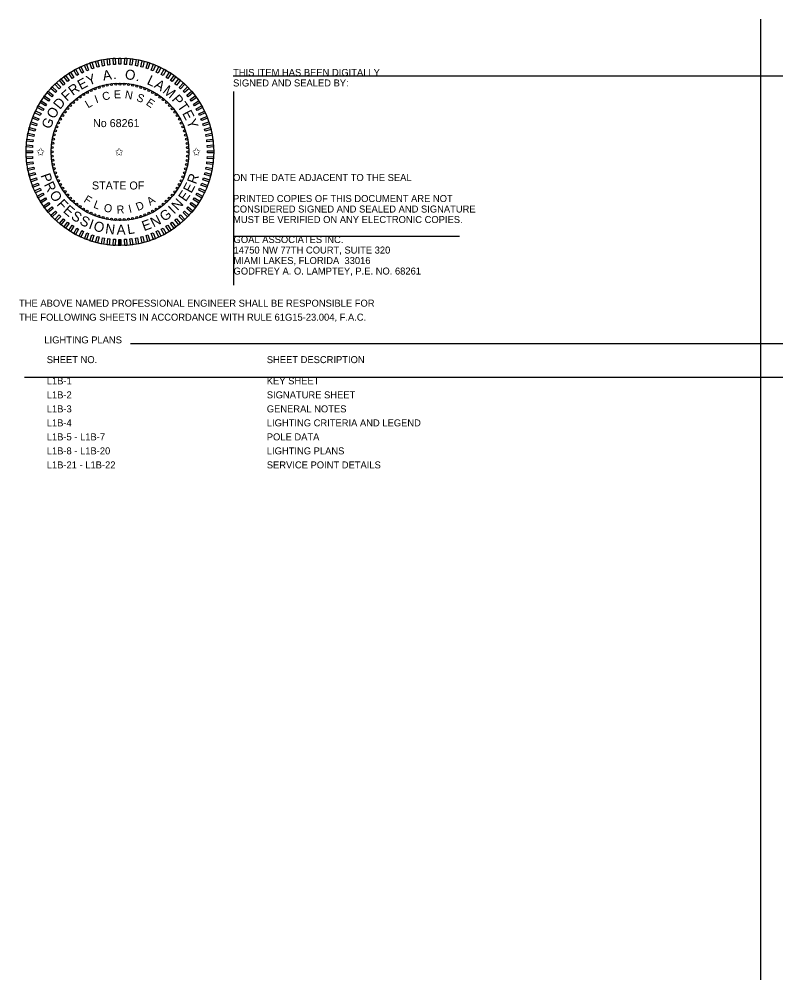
# Model space of a CAD drawing. Extents: x -811.2 to -795, y -2307.6 to -2235.1.
# Drawn here: x -810.5 to -802.94, y -2244.66 to -2235.06 of the extents above; entities that cross this region are included whole.
import ezdxf

# ---------------------------------------------------------------- set-up
doc = ezdxf.new("R2010")
doc.units = 0
for name, color, linetype in [('AdhocPoint_dp', 7, 'Continuous'), ('Logo_dp', 7, 'Continuous'), ('TeleMisc', 7, 'Continuous'), ('TextDetails', 7, 'Continuous'), ('TextMisc', 7, 'Continuous'), ('TextNotes', 7, 'Continuous')]:
    doc.layers.add(name, color=color, linetype=linetype)

msp = doc.modelspace()

# ---------------------------------------------------------------- linework, layer by layer
at = {"layer": 'AdhocPoint_dp'}
for p, q in [((-808.3596, -2235.6292), (-796.8708, -2235.6292)), ((-808.3546, -2235.7843), (-808.3546, -2237.719)), ((-808.3546, -2237.229), (-806.0979, -2237.229)), ((-809.3854, -2238.3022), (-800.7818, -2238.3022)), ((-801.9648, -2238.6414), (-810.4432, -2238.6414))]:
    msp.add_line(p, q, dxfattribs=at)
at = {"layer": 'TextDetails'}
for radius in [0.9375, 0.6875]:
    msp.add_circle((-809.4901, -2236.3877), radius, dxfattribs=at)
at = {"layer": 'TextMisc'}
for p, q in [((-809.5001, -2237.3253), (-809.5003, -2237.2628)), ((-809.4901, -2237.3252), (-809.4903, -2237.2627)), ((-809.4801, -2237.3252), (-809.4803, -2237.2627))]:
    msp.add_line(p, q, dxfattribs=at)
for points in [[(-809.5349, -2235.5138), (-809.555, -2235.5151), (-809.559, -2235.4527), (-809.5388, -2235.4515)], [(-809.4799, -2235.5127), (-809.5001, -2235.5127), (-809.5001, -2235.4503), (-809.4799, -2235.4503)], [(-809.425, -2235.5151), (-809.4452, -2235.5138), (-809.4412, -2235.4515), (-809.4211, -2235.4528)], [(-809.8535, -2235.5917), (-809.8717, -2235.6002), (-809.8983, -2235.5438), (-809.8801, -2235.5352)], [(-809.8028, -2235.5704), (-809.8215, -2235.5778), (-809.8445, -2235.5198), (-809.8258, -2235.5124)], [(-809.7508, -2235.5524), (-809.77, -2235.5586), (-809.7893, -2235.4992), (-809.7701, -2235.493)], [(-809.6979, -2235.5377), (-809.7174, -2235.5427), (-809.7329, -2235.4822), (-809.7134, -2235.4772)], [(-809.6441, -2235.5263), (-809.6639, -2235.5301), (-809.6756, -2235.4688), (-809.6558, -2235.465)], [(-809.5897, -2235.5183), (-809.6097, -2235.5209), (-809.6175, -2235.4589), (-809.5975, -2235.4564)], [(-809.3703, -2235.5209), (-809.3904, -2235.5184), (-809.3825, -2235.4564), (-809.3625, -2235.4589)], [(-809.3162, -2235.5301), (-809.336, -2235.5263), (-809.3243, -2235.465), (-809.3045, -2235.4688)], [(-809.2626, -2235.5427), (-809.2822, -2235.5377), (-809.2667, -2235.4772), (-809.2471, -2235.4823)], [(-809.21, -2235.5587), (-809.2292, -2235.5524), (-809.2099, -2235.4931), (-809.1907, -2235.4993)], [(-809.1585, -2235.5779), (-809.1773, -2235.5705), (-809.1543, -2235.5124), (-809.1355, -2235.5199)], [(-809.1083, -2235.6003), (-809.1266, -2235.5917), (-809.1, -2235.5352), (-809.0817, -2235.5438)], [(-809.9962, -2235.6738), (-810.0125, -2235.6857), (-810.0492, -2235.6352), (-810.0329, -2235.6233)], [(-809.9504, -2235.6435), (-809.9674, -2235.6543), (-810.0009, -2235.6016), (-809.9838, -2235.5908)], [(-809.9027, -2235.616), (-809.9204, -2235.6258), (-809.9505, -2235.571), (-809.9328, -2235.5613)], [(-809.0596, -2235.6259), (-809.0773, -2235.6161), (-809.0473, -2235.5614), (-809.0296, -2235.5711)], [(-809.0127, -2235.6544), (-809.0297, -2235.6436), (-808.9962, -2235.5909), (-808.9792, -2235.6017)], [(-808.9676, -2235.6858), (-808.9839, -2235.674), (-808.9472, -2235.6234), (-808.9308, -2235.6353)], [(-810.121, -2235.7813), (-810.1348, -2235.796), (-810.1804, -2235.7533), (-810.1665, -2235.7386)], [(-810.0817, -2235.7429), (-810.0964, -2235.7567), (-810.1392, -2235.7112), (-810.1244, -2235.6974)], [(-810.04, -2235.707), (-810.0556, -2235.7199), (-810.0954, -2235.6718), (-810.0798, -2235.6589)], [(-808.9245, -2235.72), (-808.9401, -2235.7071), (-808.9003, -2235.659), (-808.8847, -2235.6719)], [(-808.8837, -2235.7568), (-808.8984, -2235.743), (-808.8557, -2235.6975), (-808.841, -2235.7113)], [(-808.8453, -2235.7962), (-808.8591, -2235.7815), (-808.8136, -2235.7387), (-808.7998, -2235.7534)], [(-810.192, -2235.8652), (-810.2039, -2235.8815), (-810.2544, -2235.8448), (-810.2426, -2235.8285)], [(-810.1579, -2235.8221), (-810.1707, -2235.8377), (-810.2188, -2235.7979), (-810.206, -2235.7823)], [(-808.8094, -2235.8378), (-808.8223, -2235.8223), (-808.7742, -2235.7825), (-808.7613, -2235.798)], [(-808.7762, -2235.8817), (-808.7881, -2235.8653), (-808.7376, -2235.8286), (-808.7257, -2235.845)], [(-810.252, -2235.9573), (-810.2617, -2235.975), (-810.3164, -2235.9449), (-810.3067, -2235.9272)], [(-810.2235, -2235.9103), (-810.2343, -2235.9273), (-810.287, -2235.8939), (-810.2762, -2235.8768)], [(-808.7459, -2235.9275), (-808.7567, -2235.9104), (-808.7039, -2235.877), (-808.6931, -2235.894)], [(-808.7184, -2235.9751), (-808.7281, -2235.9574), (-808.6734, -2235.9273), (-808.6637, -2235.945)], [(-810.2775, -2236.006), (-810.2861, -2236.0242), (-810.3426, -2235.9976), (-810.334, -2235.9794)], [(-808.694, -2236.0244), (-808.7026, -2236.0061), (-808.6461, -2235.9795), (-808.6375, -2235.9978)], [(-810.3192, -2236.1077), (-810.3254, -2236.1269), (-810.3848, -2236.1076), (-810.3786, -2236.0884)], [(-810.3, -2236.0562), (-810.3074, -2236.0749), (-810.3654, -2236.0519), (-810.358, -2236.0332)], [(-808.6728, -2236.0751), (-808.6802, -2236.0563), (-808.6222, -2236.0333), (-808.6147, -2236.0521)], [(-808.6548, -2236.127), (-808.661, -2236.1078), (-808.6016, -2236.0885), (-808.5954, -2236.1077)], [(-810.3477, -2236.2138), (-810.3515, -2236.2336), (-810.4129, -2236.2219), (-810.4091, -2236.2021)], [(-810.3351, -2236.1603), (-810.3401, -2236.1798), (-810.4006, -2236.1643), (-810.3956, -2236.1447)], [(-808.64, -2236.18), (-808.6451, -2236.1604), (-808.5846, -2236.1449), (-808.5796, -2236.1645)], [(-808.6287, -2236.2338), (-808.6325, -2236.214), (-808.5711, -2236.2023), (-808.5673, -2236.2221)], [(-810.3628, -2236.3226), (-810.3641, -2236.3428), (-810.4264, -2236.3389), (-810.4251, -2236.3187)], [(-810.357, -2236.268), (-810.3595, -2236.288), (-810.4215, -2236.2802), (-810.4189, -2236.2601)], [(-808.6207, -2236.2882), (-808.6232, -2236.2682), (-808.5613, -2236.2603), (-808.5588, -2236.2804)], [(-808.6162, -2236.343), (-808.6174, -2236.3228), (-808.5551, -2236.3189), (-808.5539, -2236.339)], [(-810.3652, -2236.3776), (-810.3652, -2236.3977), (-810.4276, -2236.3977), (-810.4276, -2236.3776)], [(-808.6151, -2236.3979), (-808.6151, -2236.3777), (-808.5527, -2236.3777), (-808.5527, -2236.3979)], [(-810.3641, -2236.4325), (-810.3628, -2236.4527), (-810.4251, -2236.4566), (-810.4264, -2236.4364)], [(-810.3595, -2236.4873), (-810.357, -2236.5073), (-810.4189, -2236.5152), (-810.4215, -2236.4951)], [(-808.6233, -2236.5075), (-808.6207, -2236.4875), (-808.5588, -2236.4953), (-808.5613, -2236.5153)], [(-808.6175, -2236.4529), (-808.6162, -2236.4327), (-808.5539, -2236.4366), (-808.5551, -2236.4568)], [(-810.3516, -2236.5417), (-810.3478, -2236.5615), (-810.4091, -2236.5732), (-810.4129, -2236.5534)], [(-810.3402, -2236.5955), (-810.3352, -2236.615), (-810.3957, -2236.6306), (-810.4007, -2236.611)], [(-808.6451, -2236.6152), (-808.6401, -2236.5957), (-808.5796, -2236.6112), (-808.5846, -2236.6307)], [(-808.6325, -2236.5617), (-808.6287, -2236.5419), (-808.5674, -2236.5536), (-808.5712, -2236.5734)], [(-810.3255, -2236.6485), (-810.3192, -2236.6677), (-810.3786, -2236.6869), (-810.3849, -2236.6677)], [(-810.3075, -2236.7004), (-810.3, -2236.7192), (-810.3581, -2236.7421), (-810.3655, -2236.7234)], [(-808.6803, -2236.7193), (-808.6729, -2236.7006), (-808.6148, -2236.7236), (-808.6222, -2236.7423)], [(-808.6611, -2236.6678), (-808.6548, -2236.6486), (-808.5954, -2236.6679), (-808.6017, -2236.6871)], [(-810.2862, -2236.7511), (-810.2776, -2236.7694), (-810.3341, -2236.7959), (-810.3427, -2236.7777)], [(-808.7027, -2236.7695), (-808.6941, -2236.7513), (-808.6376, -2236.7778), (-808.6462, -2236.7961)], [(-810.2618, -2236.8004), (-810.2521, -2236.8181), (-810.3068, -2236.8481), (-810.3165, -2236.8304)], [(-810.2344, -2236.848), (-810.2236, -2236.8651), (-810.2763, -2236.8985), (-810.2871, -2236.8815)], [(-810.204, -2236.8938), (-810.1922, -2236.9102), (-810.2427, -2236.9469), (-810.2545, -2236.9305)], [(-808.7882, -2236.9103), (-808.7763, -2236.894), (-808.7258, -2236.9307), (-808.7377, -2236.947)], [(-808.7568, -2236.8652), (-808.746, -2236.8482), (-808.6932, -2236.8816), (-808.704, -2236.8987)], [(-808.7282, -2236.8182), (-808.7185, -2236.8005), (-808.6638, -2236.8306), (-808.6735, -2236.8483)], [(-810.1708, -2236.9377), (-810.158, -2236.9532), (-810.2061, -2236.993), (-810.2189, -2236.9775)], [(-810.135, -2236.9793), (-810.1211, -2236.994), (-810.1667, -2237.0368), (-810.1805, -2237.0221)], [(-808.8592, -2236.9942), (-808.8454, -2236.9795), (-808.7999, -2237.0222), (-808.8137, -2237.0369)], [(-808.8224, -2236.9534), (-808.8095, -2236.9378), (-808.7614, -2236.9776), (-808.7743, -2236.9932)], [(-810.0965, -2237.0186), (-810.0818, -2237.0325), (-810.1246, -2237.078), (-810.1393, -2237.0642)], [(-810.0557, -2237.0555), (-810.0402, -2237.0683), (-810.08, -2237.1164), (-810.0955, -2237.1036)], [(-808.9402, -2237.0685), (-808.9247, -2237.0556), (-808.8848, -2237.1037), (-808.9004, -2237.1166)], [(-808.8985, -2237.0326), (-808.8838, -2237.0188), (-808.8411, -2237.0643), (-808.8558, -2237.0781)], [(-810.0127, -2237.0897), (-809.9964, -2237.1015), (-810.0331, -2237.152), (-810.0494, -2237.1402)], [(-809.9676, -2237.1211), (-809.9505, -2237.1319), (-809.984, -2237.1846), (-810.001, -2237.1738)], [(-809.9206, -2237.1496), (-809.9029, -2237.1594), (-809.933, -2237.2141), (-809.9507, -2237.2043)], [(-809.8719, -2237.1752), (-809.8536, -2237.1838), (-809.8802, -2237.2402), (-809.8985, -2237.2317)], [(-809.1268, -2237.1838), (-809.1085, -2237.1752), (-809.0819, -2237.2317), (-809.1002, -2237.2403)], [(-809.0775, -2237.1594), (-809.0598, -2237.1497), (-809.0297, -2237.2044), (-809.0474, -2237.2142)], [(-809.0299, -2237.132), (-809.0128, -2237.1212), (-808.9794, -2237.1739), (-808.9964, -2237.1847)], [(-808.984, -2237.1016), (-808.9677, -2237.0898), (-808.931, -2237.1403), (-808.9473, -2237.1522)], [(-809.8217, -2237.1976), (-809.8029, -2237.205), (-809.8259, -2237.2631), (-809.8447, -2237.2556)], [(-809.7702, -2237.2168), (-809.751, -2237.223), (-809.7703, -2237.2824), (-809.7895, -2237.2762)], [(-809.7176, -2237.2327), (-809.698, -2237.2378), (-809.7136, -2237.2982), (-809.7331, -2237.2932)], [(-809.6641, -2237.2454), (-809.6443, -2237.2491), (-809.656, -2237.3105), (-809.6758, -2237.3067)], [(-809.6099, -2237.2546), (-809.5899, -2237.2571), (-809.5977, -2237.3191), (-809.6177, -2237.3165)], [(-809.5552, -2237.2604), (-809.5351, -2237.2617), (-809.539, -2237.324), (-809.5592, -2237.3227)], [(-809.5003, -2237.2628), (-809.4801, -2237.2628), (-809.4801, -2237.3252), (-809.5003, -2237.3252)], [(-809.4453, -2237.2617), (-809.4252, -2237.2604), (-809.4213, -2237.3227), (-809.4414, -2237.324)], [(-809.3906, -2237.2571), (-809.3705, -2237.2546), (-809.3627, -2237.3166), (-809.3827, -2237.3191)], [(-809.3362, -2237.2492), (-809.3163, -2237.2454), (-809.3046, -2237.3067), (-809.3245, -2237.3105)], [(-809.2824, -2237.2378), (-809.2628, -2237.2328), (-809.2473, -2237.2933), (-809.2668, -2237.2983)], [(-809.2294, -2237.2231), (-809.2102, -2237.2169), (-809.1909, -2237.2762), (-809.2101, -2237.2825)], [(-809.1775, -2237.2051), (-809.1587, -2237.1976), (-809.1357, -2237.2557), (-809.1545, -2237.2631)]]:
    msp.add_lwpolyline(points, close=True, dxfattribs=at)
for centre in [(-809.6989, -2235.7433), (-809.6581, -2235.7314), (-809.6165, -2235.7222), (-809.5745, -2235.7155), (-809.5321, -2235.7116), (-809.4896, -2235.7103), (-809.447, -2235.7116), (-809.4047, -2235.7157), (-809.3626, -2235.7224), (-809.3211, -2235.7317), (-809.2802, -2235.7436), (-809.8879, -2235.8393), (-809.8527, -2235.8154), (-809.816, -2235.7938), (-809.7781, -2235.7745), (-809.739, -2235.7576), (-809.2402, -2235.7581), (-809.2012, -2235.775), (-809.1633, -2235.7943), (-809.1266, -2235.816), (-809.0915, -2235.84), (-809.9836, -2235.9236), (-809.9535, -2235.8935), (-809.9215, -2235.8654), (-809.0579, -2235.8661), (-809.026, -2235.8943), (-808.9959, -2235.9244), (-810.0618, -2236.0243), (-810.0379, -2235.9891), (-810.0118, -2235.9555), (-808.9678, -2235.9563), (-808.9417, -2235.99), (-808.9178, -2236.0252), (-810.1198, -2236.1378), (-810.1029, -2236.0988), (-810.0835, -2236.0609), (-808.8962, -2236.0619), (-808.8769, -2236.0998), (-810.1462, -2236.2187), (-810.1343, -2236.1779), (-808.86, -2236.1389), (-808.8456, -2236.1789), (-808.8338, -2236.2198), (-810.1622, -2236.3023), (-810.1555, -2236.2602), (-808.8245, -2236.2614), (-808.8179, -2236.3034), (-810.1676, -2236.3872), (-810.1662, -2236.3446), (-808.814, -2236.3458), (-808.8127, -2236.3883), (-810.1663, -2236.4297), (-810.1623, -2236.4721), (-810.1557, -2236.5141), (-808.8248, -2236.5152), (-808.8181, -2236.4732), (-808.814, -2236.4308), (-810.1464, -2236.5557), (-810.1346, -2236.5966), (-808.846, -2236.5976), (-808.8341, -2236.5568), (-810.1202, -2236.6366), (-810.1034, -2236.6757), (-810.0841, -2236.7136), (-808.8774, -2236.6767), (-808.8604, -2236.6377), (-810.0624, -2236.7503), (-810.0385, -2236.7855), (-808.9424, -2236.7864), (-808.9184, -2236.7512), (-808.8967, -2236.7146), (-810.0125, -2236.8191), (-809.9844, -2236.8511), (-809.9543, -2236.8812), (-809.0268, -2236.882), (-808.9967, -2236.8519), (-808.9685, -2236.82), (-809.9224, -2236.9094), (-809.8888, -2236.9355), (-809.8536, -2236.9594), (-809.817, -2236.9811), (-809.7791, -2237.0005), (-809.2022, -2237.001), (-809.1642, -2236.9817), (-809.1276, -2236.96), (-809.0924, -2236.9362), (-809.0587, -2236.9101), (-809.74, -2237.0174), (-809.7, -2237.0319), (-809.6591, -2237.0438), (-809.6176, -2237.0531), (-809.5756, -2237.0598), (-809.5332, -2237.0638), (-809.4901, -2237.0652), (-809.4481, -2237.0639), (-809.4058, -2237.0599), (-809.3637, -2237.0533), (-809.3222, -2237.0441), (-809.2813, -2237.0322), (-809.2413, -2237.0178)]:
    msp.add_circle(centre, 0.01, dxfattribs=at)
at = {"layer": 'TextNotes'}
msp.add_line((-803.0858, -2244.6621), (-803.0858, -2235.0621), dxfattribs=at)

# ---------------------------------------------------------------- texts
at = {"layer": 'Logo_dp'}
for s, p in [('THIS ITEM HAS BEEN DIGITALLY', (-808.3596, -2235.6292)), ('SIGNED AND SEALED BY:', (-808.3596, -2235.7342)), ('ON THE DATE ADJACENT TO THE SEAL', (-808.3596, -2236.6792)), ('PRINTED COPIES OF THIS DOCUMENT ARE NOT ', (-808.3596, -2236.8892)), ('CONSIDERED SIGNED AND SEALED AND SIGNATURE ', (-808.3596, -2236.9942)), ('MUST BE VERIFIED ON ANY ELECTRONIC COPIES.', (-808.3596, -2237.0992)), ('GOAL ASSOCIATES INC.', (-808.3546, -2237.299)), ('14750 NW 77TH COURT, SUITE 320', (-808.3546, -2237.404)), ('MIAMI LAKES, FLORIDA  33016', (-808.3546, -2237.509)), ('GODFREY A. O. LAMPTEY, P.E. NO. 68261', (-808.3546, -2237.614)), ('THE ABOVE NAMED PROFESSIONAL ENGINEER SHALL BE RESPONSIBLE FOR ', (-810.4987, -2237.9352)), ('THE FOLLOWING SHEETS IN ACCORDANCE WITH RULE 61G15-23.004, F.A.C.', (-810.4987, -2238.0752)), ('LIGHTING PLANS', (-810.245, -2238.3022))]:
    msp.add_text(s, height=0.07, dxfattribs=at).set_placement(p)
at = {"layer": 'TeleMisc'}
for s, p in [('SHEET NO.', (-810.2215, -2238.4992)), ('SHEET DESCRIPTION', (-808.0226, -2238.4992)), ('L1B-1', (-810.2215, -2238.7114)), ('KEY SHEET', (-808.0226, -2238.7114)), ('L1B-2', (-810.2215, -2238.8514)), ('SIGNATURE SHEET', (-808.0226, -2238.8514)), ('L1B-3', (-810.2215, -2238.9914)), ('GENERAL NOTES', (-808.0226, -2238.9914)), ('L1B-4', (-810.2215, -2239.1314)), ('LIGHTING CRITERIA AND LEGEND', (-808.0226, -2239.1314)), ('L1B-5 - L1B-7', (-810.2215, -2239.2714)), ('POLE DATA', (-808.0226, -2239.2714)), ('L1B-8 - L1B-20', (-810.2215, -2239.4114)), ('LIGHTING PLANS', (-808.0226, -2239.4114)), ('L1B-21 - L1B-22', (-810.2215, -2239.5514)), ('SERVICE POINT DETAILS', (-808.0226, -2239.5514))]:
    msp.add_text(s, height=0.07, dxfattribs=at).set_placement(p)
at = {"layer": 'TextMisc'}
for s, height, rotation, p in [('E', 0.1, 28.10553, (-809.8806, -2235.7716)), ('Y', 0.1, 21.06329, (-809.8021, -2235.7283)), ('A', 0.1, 8.80884, (-809.6551, -2235.6771)), ('.', 0.1, 1.04184, (-809.5575, -2235.6613)), ('O', 0.1, 352.18771, (-809.4449, -2235.6596)), ('L', 0.1, 334.67271, (-809.2279, -2235.707)), ('R', 0.1, 35.92688, (-809.9609, -2235.8304)), ('.', 0.1, 343.52684, (-809.3358, -2235.6747)), ('A', 0.1, 328.40959, (-809.1552, -2235.7397)), ('M', 0.1, 320.6426, (-809.0707, -2235.7909)), ('F', 0.1, 42.37723, (-810.0205, -2235.8868)), ('I', 0.08, 20.01168, (-809.7258, -2235.9037)), ('C', 0.08, 12.20255, (-809.6579, -2235.8761)), ('E', 0.08, 0.41861, (-809.5498, -2235.8527)), ('N', 0.08, 349.29143, (-809.4455, -2235.8512)), ('S', 0.08, 337.02207, (-809.3325, -2235.8729)), ('P', 0.1, 311.19658, (-808.9784, -2235.8678)), ('D', 0.1, 50.8569, (-810.0886, -2235.9705)), ('L', 0.08, 30.40215, (-809.8093, -2235.9541)), ('E', 0.08, 325.86633, (-809.2358, -2235.9132)), ('T', 0.1, 304.45632, (-808.9209, -2235.9315)), ('O', 0.1, 59.51777, (-810.1446, -2236.0654)), ('E', 0.1, 297.63152, (-808.8707, -2236.0023)), ('G', 0.1, 68.0518, (-810.1851, -2236.1661)), ('Y', 0.1, 290.58928, (-808.8281, -2236.0812)), ('P', 0.1, 289.40551, (-810.2848, -2236.6223)), ('R', 0.1, 69.5134, (-808.7299, -2236.7174)), ('R', 0.1, 296.14576, (-810.2518, -2236.714)), ('E', 0.1, 62.47116, (-808.7761, -2236.8082)), ('O', 0.1, 303.96711, (-810.2003, -2236.8146)), ('E', 0.1, 55.42892, (-808.833, -2236.8925)), ('F', 0.1, 312.62798, (-810.1279, -2236.9167)), ('F', 0.08, 328.72408, (-809.8582, -2236.8843)), ('L', 0.08, 339.29159, (-809.7609, -2236.9434)), ('D', 0.08, 22.01279, (-809.312, -2236.9796)), ('A', 0.08, 34.49917, (-809.1883, -2236.9271)), ('N', 0.1, 47.17876, (-808.9123, -2236.9816)), ('E', 0.1, 319.07833, (-810.0645, -2236.985)), ('S', 0.1, 326.12056, (-809.9869, -2237.0509)), ('O', 0.08, 349.68206, (-809.6562, -2236.9831)), ('R', 0.08, 2.33977, (-809.5217, -2237.005)), ('I', 0.08, 14.20366, (-809.3941, -2236.9984)), ('G', 0.1, 35.11153, (-809.0492, -2237.0893)), ('I', 0.1, 43.64556, (-808.9499, -2237.0161)), ('S', 0.1, 333.193, (-809.9015, -2237.107)), ('I', 0.1, 340.26543, (-809.8098, -2237.1522)), ('O', 0.1, 343.79863, (-809.7621, -2237.1704)), ('E', 0.1, 19.81912, (-809.2498, -2237.1807)), ('N', 0.1, 26.86136, (-809.1544, -2237.1453)), ('N', 0.1, 352.45949, (-809.6411, -2237.2025)), ('A', 0.1, 0.70966, (-809.5227, -2237.2157)), ('L', 0.1, 8.47665, (-809.4105, -2237.2125))]:
    msp.add_text(s, height=height, rotation=rotation, dxfattribs=at).set_placement(p)
for s, p in [('No 68261', (-809.7591, -2236.1405)), ('✩', (-810.3251, -2236.4257)), ('✩', (-809.5404, -2236.4257)), ('✩', (-808.7685, -2236.4257)), ('STATE OF', (-809.7698, -2236.7639))]:
    msp.add_text(s, height=0.08, dxfattribs=at).set_placement(p)

doc.saveas('drawing.dxf')
